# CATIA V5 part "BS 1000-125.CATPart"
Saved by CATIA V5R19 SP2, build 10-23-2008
Part number: BS 1000-125
Bounding box of the stored display mesh (mm): x -24.865 to 24.865, y -24.997 to 24.997, z 0 to 288
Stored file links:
  C:\Users\Bora\Desktop\3D Katı model\BS serisi\BS 1000\BS 1000-125.CATPart
  C:\Program Files\Dassault Systemes\B19\intel_a\reffiles\standard\MetricThickPitch.txt
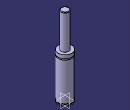
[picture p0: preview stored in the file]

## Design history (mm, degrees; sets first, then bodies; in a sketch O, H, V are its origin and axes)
Body1 (main body)
  Sketch1 on yz-plane, origin (0, 0, 0), H (0, 1, 0), V (0, 0, 1)
    point P2 (14, 286)
    line L1 (14, 286) -> (14, 162)
    point P3 (25, 149.5)
    line L2 (25, 162) -> (25, 149.5)
    point P6 (25, 145.5)
    line L3 (25, 145.5) -> (25, 7.5)
    line L4 (25, 4) -> (25, 0)
    point P9 (25, 145.5)
    point P10 (25, 149.5)
    arc A1 centre (25, 147.5) radius 2 from (25, 149.5) to (25, 145.5) ccw
    point P12 (14, 286)
    arc A2 centre (12, 286) radius 2 from (14, 286) to (12, 288) ccw
    point P13 (22.5, 4)
    point P14 (22.5, 4)
    line L5 (22.5, 7.5) -> (22.5, 4)
    line L6 (12, 288) -> (0, 288)
    point P16 (0, 288)
    line L7 (14, 162) -> (25, 162)
    line L8 (0, 0) -> (25, 0)
    line L9 (22.5, 7.5) -> (25, 7.5)
    line L10 (22.5, 4) -> (25, 4)
    coincidence: P16 V, P2 P12, P3 P10, P6 P9, P13 P14
    tangency: L6 A2
    horizontal: L7 H, L8 H, L9 H, L10 H
  Shaft1: profile Sketch1, axis Sketch1.V, angle 360
  Sketch2 on face of Shaft1 from Sketch1.L8, origin (0, 0, 0), H (1, 0, 0), V (0, -1, 0)
    point P1 (10, 0)
    distance P1 V = 10
  Hole1: placed by Sketch2, at (10, 0, 0) direction (0, 0, 1), diameter 6.647, depth 6, threaded "M8", thread diameter 8, thread depth 6, pitch 1.25
  CircPattern1: of Hole1, instances 2, angular step 180, axis from xy-plane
